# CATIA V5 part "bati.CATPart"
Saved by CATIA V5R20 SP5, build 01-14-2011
Part number: bati
Bounding box of the stored display mesh (mm): x 0 to 22, y -15 to 385, z -17 to 17
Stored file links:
  F:\projet\yyang_IAO\bati.CATPart
  F:\projet\yyang_IAO\iao.CATProduct
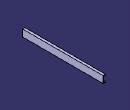
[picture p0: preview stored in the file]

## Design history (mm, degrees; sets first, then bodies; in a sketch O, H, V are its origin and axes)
External parameters (linked from other documents)
  External.epaisseur = 10 mm
  `External.rayon de liaison` = 5 mm
Set1
  Plane1: linked copy from another document
  Point1: linked copy from another document
Set2
  Plane2: type Offset, RefPlane Plane1, Offset 10 {= External.epaisseur}
Body1 (main body)
  Sketch1 on Plane2, origin (10, 0, 0), H (0, 1, 0), V (0, 0, 1)
    line L1 (-15, 17) -> (385, 17)
    line L2 (385, 17) -> (385, -17)
    line L3 (385, -17) -> (-15, -17)
    line L4 (-15, -17) -> (-15, 17)
    reference projected point E1 (0, 0) from Point1
    reference projected point E2 (0, 0) from Point1
    reference projected point E3 (0, 0) from Point1
    distance L4 E1 = 15
    distance L1 E2 = 17
    distance L3 E3 = 17
    distance L2 L4 = 400
    horizontal: L1 H, L3 H
    vertical: L2 V, L4 V
  Pad1: profile Sketch1, direction (1, 0, 0), length 12
  Sketch2 on start face of Pad1, origin (10, 0, 0), H (0, -1, 0), V (0, 0, 1)
    line L1 (-395, 12.5) -> (-35, 12.5)
    line L2 (-35, 12.5) -> (-35, -12.5)
    line L3 (-35, -12.5) -> (-395, -12.5)
    line L4 (-395, -12.5) -> (-395, 12.5)
    reference projected line E1 (15, 17) -> (15, -17) from edge [start face of Pad1 | face of Pad1 from Sketch1.L4]
    reference projected line E2 (-385, 17) -> (15, 17) from edge [start face of Pad1 | face of Pad1 from Sketch1.L1]
    reference projected line E3 (15, -17) -> (-385, -17) from edge [start face of Pad1 | face of Pad1 from Sketch1.L3]
    distance L2 E1 = 50
    distance L1 E2 = 4.5
    distance L3 E3 = 4.5
    distance L4 L2 = 360
    horizontal: L1 H, L3 H
    vertical: L2 V, L4 V
  Pocket1: profile Sketch2, direction (1, 0, 0), length 10
  Sketch3 on start face of Pad1, origin (10, 0, 0), H (0, -1, 0), V (0, 0, 1)
    circle A1 centre (0, 0) radius 5
    point P1 (0, 0)
    reference projected point E1 (0, 0) from Point1
    reference projected point E2 (0, 0) from Point1
    distance A1 E2 = 5 {= `External.rayon de liaison`}
    coincidence: E1 P1
  Pad2: profile Sketch3, direction (-1, 0, 0), length 10 {= External.epaisseur}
